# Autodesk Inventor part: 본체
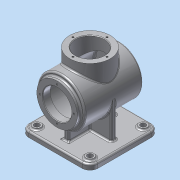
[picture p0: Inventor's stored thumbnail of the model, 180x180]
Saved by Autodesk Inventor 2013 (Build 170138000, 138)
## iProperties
Created: 2015-07
Part Number: 본체
Material: 알루미늄 6061
Document SubType Name: Modeling
Designer: dgall
Density: 2.71 g/cm^3
Mass: 1277.59 g
Surface Area: 1267.74 cm^2
Volume: 471.434 cm^3
Author: dgall
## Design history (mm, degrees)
sketch "스케치1"
  geometry: L1 (-65, 65)-(65, 65); L2 (65, 65)-(65, -65); L3 (65, -65)-(-65, -65); L4 (-65, -65)-(-65, 65); 5 further points
  constraints: 8 end point, 4 midpoint, 2 horizontal alignment, 2 parallel, 2 vertical alignment, 1 horizontal, 1 perpendicular
  dimensions: "d0" = 130 distance of L1.start L1.end; "d2" = 130 distance of L1.end L2.end
extrude "돌출1" new body sketch "스케치1" distance "d3" = 10; taper "d4" = 0 deg
node "작업 평면1"
sketch "스케치3"
  geometry: L1 (0, -65)-(0, 65) reference; C1 r 45 at (78, 0); 2 further points
  constraints: 1 centre point, 1 horizontal alignment, 1 midpoint
  dimensions: "d14" = 78 distance from line of C1.centre L1; "d15" = 90 diameter of C1
extrude "돌출2" join sketch "스케치3" distance "d16" = 110; taper "d17" = 0 deg
sketch "스케치4"
  geometry: C1 r 45 at (0, 0) reference; C2 r 38 at (0, 0); 1 further point
  constraints: 1 centre point, 1 coincident
  dimensions: "d18" = 76 diameter of C2
extrude "돌출3" join sketch "스케치4" distance "d20" = 7; taper "d21" = 0 deg
sketch "스케치5"
  geometry: L1 (-55, 123)-(55, 123) reference; L2 (55, 123)-(55, 33) reference; L3 (55, 33)-(-55, 33) reference; L4 (-55, 33)-(-55, 40) reference; L5 (-55, 40)-(-62, 40) reference; L6 (-62, 40)-(-62, 116) reference; L7 (-62, 116)-(-55, 116) reference; L8 (-55, 116)-(-55, 123) reference; L9 (65, 10)-(65, 0) reference; L10 (65, 0)-(-65, 0) reference; L11 (-65, 0)-(-65, 10) reference; L12 (-65, 10)-(65, 10) reference; L13 (-62, 78)-(55, 78); L14 (-62, 105)-(-48, 105); L15 (-48, 105)-(-48, 118); L16 (-48, 118)-(48, 118); L17 (48, 118)-(48, 78); L18 (-62, 105)-(-62, 78); 1 further point
  constraints: 12 end point, 3 perpendicular, 2 midpoint, 2 point on line, 1 collinear, 1 parallel
  dimensions: "d22" = 14 distance of L14.start L14.end; "d24" = 54 diameter of L14 L13; "d25" = 96 distance of L15.end L16.end; "d26" = 80 diameter of L16 L13
revolve "회전1" sketch "스케치5" stored, may be unused: angle "d27" = 90 deg
sketch "스케치6"
  geometry: L1 (-5, 45)-(5, 45); L2 (5, 45)-(5, -45); L3 (5, -45)-(-5, -45); L4 (-5, -45)-(-5, 45); L5 (-45, 5)-(45, 5); L6 (45, 5)-(45, -5); L7 (45, -5)-(-45, -5); L8 (-45, -5)-(-45, 5); 8 further points
  constraints: 16 end point, 7 midpoint, 4 parallel, 4 vertical alignment, 3 horizontal alignment, 2 horizontal, 2 perpendicular
  dimensions: "d28" = 10 distance of L1.start L1.end; "d30" = 90 distance between parallel lines of L3 L1; "d31" = 90 distance of L6.end L7.end; "d32" = 10 distance between parallel lines of L7 L5
extrude "돌출4" join sketch "스케치6" stored distance "d33" = 7; taper "d34" = 0 deg
node "작업 평면2"
sketch "스케치7"
  geometry: C1 r 38 at (0, 0); C2 r 27 at (0, 0); 1 further point
  constraints: 2 centre point, 2 coincident
  dimensions: "d36" = 76 diameter of C1; "d38" = 54 diameter of C2
extrude "돌출5" join sketch "스케치7" stored distance "d39" = 7; taper "d40" = 0 deg
extrude "돌출6" cut sketch "스케치7" stored distance "d41" = 7; taper "d42" = 0 deg
sketch "스케치8"
  geometry: L1 (-45, -5)-(-45, 5) reference; L2 (-45, 5)-(-5, 5) reference; L3 (-5, 5)-(-5, 45) reference; L4 (-5, 45)-(5, 45) reference; L5 (5, 45)-(5, 5) reference; L6 (5, 5)-(45, 5) reference; L7 (45, 5)-(45, -5) reference; L8 (45, -5)-(5, -5) reference; L9 (5, -5)-(5, -45) reference; L10 (5, -45)-(-5, -45) reference; L11 (-5, -45)-(-5, -5) reference; L12 (-5, -5)-(-45, -5) reference; L13 (-65, -65)-(-65, 65) reference; L14 (-65, 65)-(65, 65) reference; L15 (65, 65)-(65, -65) reference; L16 (65, -65)-(-65, -65) reference; C1 r 7.5 at (-50, 50); 1 further point
  constraints: 1 centre point
  dimensions: "d43" = 15 diameter of C1; "d46" = 50 horizontal distance of C1.centre point (0, 0); "d47" = 50 horizontal distance of point (0, 0) C1.centre
extrude "돌출7" join sketch "스케치8" distance "d48" = 3; taper "d49" = 0 deg
sketch "스케치9"
  geometry: C1 r 7.5 at (0, 0) reference; C2 r 5 at (0, 0); 1 further point
  constraints: 1 centre point, 1 coincident
  dimensions: "d50" = 10 diameter of C2
extrude "돌출8" cut sketch "스케치9" stored distance "d52" = 3; taper "d53" = 0 deg
sketch "스케치10" dims "d60" = 64
  geometry: C1 r 27 at (0, 0) reference; C2 r 38 at (0, 0) reference; 3 further points
  constraints: 2 vertical alignment, 1 coincident, 2 other
hole "구멍1" sketch "스케치10" at (0, 32) diameter "d62" = 3.242; stored, may be unused: countersink angle "d66" = 90 deg, drill point angle "d68" = 118 deg; dims "d63" = 8, "d64" = 4, "d65" = 2, "d67" = 10
sketch "스케치11" dims "d72" = 64
  geometry: C1 r 27 at (0, 0) reference; C2 r 38 at (0, 0) reference; 2 further points
  constraints: 2 vertical alignment, 1 coincident, 2 other
hole "구멍2" sketch "스케치11" at (0, 32) diameter "d74" = 3.242; stored, may be unused: countersink angle "d78" = 90 deg, drill point angle "d80" = 118 deg; dims "d75" = 8, "d76" = 4, "d77" = 2, "d79" = 10
sketch "스케치12"
  geometry: C1 r 45 at (0, 0) reference; 2 further points
  constraints: 1 coincident, 1 other
feature "엠보싱1" sketch "스케치12" dims "d0" = 130, "d2" = 130, "d84" = 0.5, "d85" = 0
fillet "모깎기1" dims "d86" = 15
fillet "모깎기2" dims "d87" = 3
fillet "모깎기3" dims "d88" = 3
chamfer "모따기1" distance "d89" = 1; stored, may be unused: second distance "d90" = 2, angle "d91" = 45 deg
fillet "모깎기4" dims "d92" = 3
node "솔리드1"
pattern_linear "직사각형 패턴1"
pattern_circular "원형 패턴1" dims angle "d70" = 360 deg
pattern_circular "원형 패턴2" dims angle "d82" = 360 deg
node "절단 모서리 투영1"
node "절단 모서리 투영2"
other parameters: "d13" = -55
